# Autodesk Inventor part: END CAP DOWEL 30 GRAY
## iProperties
Created: 2012-02
Part Number: END CAP DOWEL 30 GRAY
Material: ABS Plastic
Document SubType Name: Modeling
Designer: Administrator
Mass: 0.132873 g
Surface Area: 1.35153 cm^2
Volume: 0.125352 cm^3
Density: 1.06 g/cm^3
Author: Administrator
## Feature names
1. Extrusion1
2. Chamfer1
